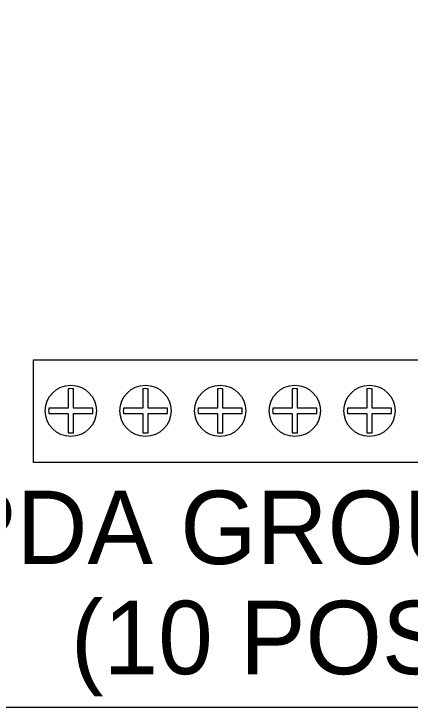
# Model space of a CAD drawing. Extents: x 99862 to 103680, y 99470 to 102076.
# Drawn here: x 101152.8 to 101239.1, y 101106.5 to 101257.6 of the extents above; entities that cross this region are included whole.
import ezdxf

# ---------------------------------------------------------------- set-up
doc = ezdxf.new("R2010")
doc.units = 0
doc.layers.add('Level 20', color=7, linetype='Continuous')
doc.layers.add('Level 26', color=7, linetype='Continuous')

msp = doc.modelspace()

# ---------------------------------------------------------------- linework, layer by layer
at = {"layer": 'Level 26'}
for p, q in [((101164.64, 101174.4), (101164.64, 101171.65)), ((101165.76, 101171.65), (101165.76, 101174.4)), ((101180.91, 101174.4), (101180.91, 101171.65)), ((101182.03, 101171.65), (101182.03, 101174.4)), ((101197.18, 101174.4), (101197.18, 101171.65)), ((101198.3, 101171.65), (101198.3, 101174.4)), ((101213.45, 101174.4), (101213.45, 101171.65)), ((101214.57, 101171.65), (101214.57, 101174.4)), ((101229.72, 101174.4), (101229.72, 101171.65)), ((101230.84, 101171.65), (101230.84, 101174.4)), ((101164.64, 101171.65), (101161.89, 101171.65)), ((101168.5, 101171.65), (101165.76, 101171.65)), ((101180.91, 101171.65), (101178.16, 101171.65)), ((101184.77, 101171.65), (101182.03, 101171.65)), ((101197.18, 101171.65), (101194.43, 101171.65)), ((101201.04, 101171.65), (101198.3, 101171.65)), ((101213.45, 101171.65), (101210.71, 101171.65)), ((101217.31, 101171.65), (101214.57, 101171.65)), ((101229.72, 101171.65), (101226.98, 101171.65)), ((101233.58, 101171.65), (101230.84, 101171.65)), ((101161.89, 101170.53), (101164.64, 101170.53)), ((101164.64, 101170.53), (101164.64, 101167.79)), ((101165.76, 101167.79), (101165.76, 101170.53)), ((101165.76, 101170.53), (101168.5, 101170.53)), ((101178.16, 101170.53), (101180.91, 101170.53)), ((101180.91, 101170.53), (101180.91, 101167.79)), ((101182.03, 101167.79), (101182.03, 101170.53)), ((101182.03, 101170.53), (101184.77, 101170.53)), ((101194.43, 101170.53), (101197.18, 101170.53)), ((101197.18, 101170.53), (101197.18, 101167.79)), ((101198.3, 101167.79), (101198.3, 101170.53)), ((101198.3, 101170.53), (101201.04, 101170.53)), ((101210.71, 101170.53), (101213.45, 101170.53)), ((101213.45, 101170.53), (101213.45, 101167.79)), ((101214.57, 101167.79), (101214.57, 101170.53)), ((101214.57, 101170.53), (101217.31, 101170.53)), ((101226.98, 101170.53), (101229.72, 101170.53)), ((101229.72, 101170.53), (101229.72, 101167.79)), ((101230.84, 101167.79), (101230.84, 101170.53)), ((101230.84, 101170.53), (101233.58, 101170.53))]:
    msp.add_line(p, q, dxfattribs=at)
for points in [[(101878.1, 101455.48), (101003.1, 101455.48), (101003.1, 101106.48), (101878.1, 101106.48)], [(101157.06, 101159.82), (101157.06, 101182.19), (101321.32, 101182.19), (101321.32, 101159.82)]]:
    msp.add_lwpolyline(points, close=True, dxfattribs=at)
for centre in [(101165.2, 101171.09), (101181.47, 101171.09), (101197.74, 101171.09), (101214.01, 101171.09), (101230.28, 101171.09)]:
    msp.add_circle(centre, 5.58, dxfattribs=at)
for centre, start, end in [((101165.2, 101171.09), 83.3581, 96.6419), ((101181.47, 101171.09), 83.3581, 96.6419), ((101197.74, 101171.09), 83.3581, 96.6419), ((101214.01, 101171.09), 83.3581, 96.6419), ((101230.28, 101171.09), 83.3581, 96.6419), ((101165.2, 101171.09), 173.3581, 186.6419), ((101165.2, 101171.09), 353.3581, 6.6419), ((101181.47, 101171.09), 173.3581, 186.6419), ((101181.47, 101171.09), 353.3581, 6.6419), ((101197.74, 101171.09), 173.3581, 186.6419), ((101197.74, 101171.09), 353.3581, 6.6419), ((101214.01, 101171.09), 173.3581, 186.6419), ((101214.01, 101171.09), 353.3581, 6.6419), ((101230.28, 101171.09), 173.3581, 186.6419), ((101230.28, 101171.09), 353.3581, 6.6419), ((101165.2, 101171.09), 263.3581, 276.6419), ((101181.47, 101171.09), 263.3581, 276.6419), ((101197.74, 101171.09), 263.3581, 276.6419), ((101214.01, 101171.09), 263.3581, 276.6419), ((101230.28, 101171.09), 263.3581, 276.6419)]:
    msp.add_arc(centre, 4.83, start, end, dxfattribs=at)
for points in [[(101164.64, 101175.89), (101164.64, 101175.76), (101164.64, 101175.63), (101164.64, 101175.48), (101164.64, 101175.25), (101164.64, 101175), (101164.64, 101174.75), (101164.64, 101174.63), (101164.64, 101174.51), (101164.64, 101174.4)], [(101165.76, 101174.4), (101165.76, 101174.64), (101165.76, 101174.89), (101165.76, 101175.12), (101165.76, 101175.36), (101165.76, 101175.59), (101165.76, 101175.78), (101165.76, 101175.82), (101165.76, 101175.85), (101165.76, 101175.89)], [(101180.91, 101175.89), (101180.91, 101175.76), (101180.91, 101175.63), (101180.91, 101175.48), (101180.91, 101175.25), (101180.91, 101175), (101180.91, 101174.75), (101180.91, 101174.63), (101180.91, 101174.51), (101180.91, 101174.4)], [(101182.03, 101174.4), (101182.03, 101174.64), (101182.03, 101174.89), (101182.03, 101175.12), (101182.03, 101175.36), (101182.03, 101175.59), (101182.03, 101175.78), (101182.03, 101175.82), (101182.03, 101175.85), (101182.03, 101175.89)], [(101197.18, 101175.89), (101197.18, 101175.76), (101197.18, 101175.63), (101197.18, 101175.48), (101197.18, 101175.25), (101197.18, 101175), (101197.18, 101174.75), (101197.18, 101174.63), (101197.18, 101174.51), (101197.18, 101174.4)], [(101198.3, 101174.4), (101198.3, 101174.64), (101198.3, 101174.89), (101198.3, 101175.12), (101198.3, 101175.36), (101198.3, 101175.59), (101198.3, 101175.78), (101198.3, 101175.82), (101198.3, 101175.85), (101198.3, 101175.89)], [(101213.45, 101175.89), (101213.45, 101175.76), (101213.45, 101175.63), (101213.45, 101175.48), (101213.45, 101175.25), (101213.45, 101175), (101213.45, 101174.75), (101213.45, 101174.63), (101213.45, 101174.51), (101213.45, 101174.4)], [(101214.57, 101174.4), (101214.57, 101174.64), (101214.57, 101174.89), (101214.57, 101175.12), (101214.57, 101175.36), (101214.57, 101175.59), (101214.57, 101175.78), (101214.57, 101175.82), (101214.57, 101175.85), (101214.57, 101175.89)], [(101229.72, 101175.89), (101229.72, 101175.76), (101229.72, 101175.63), (101229.72, 101175.48), (101229.72, 101175.25), (101229.72, 101175), (101229.72, 101174.75), (101229.72, 101174.63), (101229.72, 101174.51), (101229.72, 101174.4)], [(101230.84, 101174.4), (101230.84, 101174.64), (101230.84, 101174.89), (101230.84, 101175.12), (101230.84, 101175.36), (101230.84, 101175.59), (101230.84, 101175.78), (101230.84, 101175.82), (101230.84, 101175.85), (101230.84, 101175.89)], [(101161.89, 101171.65), (101161.89, 101171.65), (101161.89, 101171.65), (101161.89, 101171.65), (101161.64, 101171.65), (101161.38, 101171.65), (101161.14, 101171.65), (101160.91, 101171.65), (101160.68, 101171.65), (101160.48, 101171.65), (101160.45, 101171.65), (101160.43, 101171.65), (101160.4, 101171.65)], [(101169.99, 101171.65), (101169.87, 101171.65), (101169.73, 101171.65), (101169.58, 101171.65), (101169.36, 101171.65), (101169.11, 101171.65), (101168.85, 101171.65), (101168.74, 101171.65), (101168.62, 101171.65), (101168.5, 101171.65)], [(101178.16, 101171.65), (101178.16, 101171.65), (101178.16, 101171.65), (101178.16, 101171.65), (101177.91, 101171.65), (101177.65, 101171.65), (101177.41, 101171.65), (101177.18, 101171.65), (101176.95, 101171.65), (101176.75, 101171.65), (101176.72, 101171.65), (101176.7, 101171.65), (101176.67, 101171.65)], [(101186.26, 101171.65), (101186.14, 101171.65), (101186, 101171.65), (101185.86, 101171.65), (101185.63, 101171.65), (101185.38, 101171.65), (101185.12, 101171.65), (101185.01, 101171.65), (101184.89, 101171.65), (101184.77, 101171.65)], [(101194.43, 101171.65), (101194.43, 101171.65), (101194.43, 101171.65), (101194.43, 101171.65), (101194.18, 101171.65), (101193.92, 101171.65), (101193.69, 101171.65), (101193.45, 101171.65), (101193.22, 101171.65), (101193.02, 101171.65), (101193, 101171.65), (101192.97, 101171.65), (101192.94, 101171.65)], [(101202.53, 101171.65), (101202.41, 101171.65), (101202.27, 101171.65), (101202.13, 101171.65), (101201.9, 101171.65), (101201.65, 101171.65), (101201.39, 101171.65), (101201.28, 101171.65), (101201.16, 101171.65), (101201.04, 101171.65)], [(101210.71, 101171.65), (101210.7, 101171.65), (101210.7, 101171.65), (101210.7, 101171.65), (101210.45, 101171.65), (101210.19, 101171.65), (101209.96, 101171.65), (101209.72, 101171.65), (101209.49, 101171.65), (101209.29, 101171.65), (101209.27, 101171.65), (101209.24, 101171.65), (101209.21, 101171.65)], [(101218.8, 101171.65), (101218.68, 101171.65), (101218.54, 101171.65), (101218.4, 101171.65), (101218.17, 101171.65), (101217.92, 101171.65), (101217.66, 101171.65), (101217.55, 101171.65), (101217.43, 101171.65), (101217.31, 101171.65)], [(101226.98, 101171.65), (101226.98, 101171.65), (101226.97, 101171.65), (101226.97, 101171.65), (101226.72, 101171.65), (101226.47, 101171.65), (101226.23, 101171.65), (101225.99, 101171.65), (101225.76, 101171.65), (101225.56, 101171.65), (101225.54, 101171.65), (101225.51, 101171.65), (101225.48, 101171.65)], [(101235.08, 101171.65), (101234.95, 101171.65), (101234.81, 101171.65), (101234.67, 101171.65), (101234.44, 101171.65), (101234.19, 101171.65), (101233.94, 101171.65), (101233.82, 101171.65), (101233.7, 101171.65), (101233.58, 101171.65)], [(101160.4, 101170.53), (101160.43, 101170.53), (101160.45, 101170.53), (101160.48, 101170.53), (101160.6, 101170.53), (101160.73, 101170.53), (101160.87, 101170.53), (101161.1, 101170.53), (101161.36, 101170.53), (101161.61, 101170.53), (101161.71, 101170.53), (101161.8, 101170.53), (101161.89, 101170.53)], [(101168.5, 101170.53), (101168.75, 101170.53), (101168.99, 101170.53), (101169.22, 101170.53), (101169.46, 101170.53), (101169.69, 101170.53), (101169.89, 101170.53), (101169.92, 101170.53), (101169.96, 101170.53), (101169.99, 101170.53)], [(101176.67, 101170.53), (101176.7, 101170.53), (101176.72, 101170.53), (101176.75, 101170.53), (101176.87, 101170.53), (101177.01, 101170.53), (101177.14, 101170.53), (101177.37, 101170.53), (101177.63, 101170.53), (101177.89, 101170.53), (101177.98, 101170.53), (101178.07, 101170.53), (101178.16, 101170.53)], [(101184.77, 101170.53), (101185.02, 101170.53), (101185.26, 101170.53), (101185.5, 101170.53), (101185.73, 101170.53), (101185.96, 101170.53), (101186.16, 101170.53), (101186.19, 101170.53), (101186.23, 101170.53), (101186.26, 101170.53)], [(101192.94, 101170.53), (101192.97, 101170.53), (101193, 101170.53), (101193.02, 101170.53), (101193.14, 101170.53), (101193.28, 101170.53), (101193.41, 101170.53), (101193.65, 101170.53), (101193.9, 101170.53), (101194.16, 101170.53), (101194.25, 101170.53), (101194.34, 101170.53), (101194.43, 101170.53)], [(101201.04, 101170.53), (101201.29, 101170.53), (101201.53, 101170.53), (101201.77, 101170.53), (101202, 101170.53), (101202.23, 101170.53), (101202.43, 101170.53), (101202.46, 101170.53), (101202.5, 101170.53), (101202.53, 101170.53)], [(101209.21, 101170.53), (101209.24, 101170.53), (101209.27, 101170.53), (101209.29, 101170.53), (101209.41, 101170.53), (101209.55, 101170.53), (101209.69, 101170.53), (101209.92, 101170.53), (101210.17, 101170.53), (101210.43, 101170.53), (101210.52, 101170.53), (101210.61, 101170.53), (101210.71, 101170.53)], [(101217.31, 101170.53), (101217.56, 101170.53), (101217.81, 101170.53), (101218.04, 101170.53), (101218.27, 101170.53), (101218.5, 101170.53), (101218.7, 101170.53), (101218.74, 101170.53), (101218.77, 101170.53), (101218.8, 101170.53)], [(101225.48, 101170.53), (101225.51, 101170.53), (101225.54, 101170.53), (101225.56, 101170.53), (101225.68, 101170.53), (101225.82, 101170.53), (101225.96, 101170.53), (101226.19, 101170.53), (101226.44, 101170.53), (101226.7, 101170.53), (101226.79, 101170.53), (101226.88, 101170.53), (101226.98, 101170.53)], [(101233.58, 101170.53), (101233.83, 101170.53), (101234.08, 101170.53), (101234.31, 101170.53), (101234.54, 101170.53), (101234.77, 101170.53), (101234.97, 101170.53), (101235.01, 101170.53), (101235.04, 101170.53), (101235.08, 101170.53)], [(101164.64, 101167.79), (101164.64, 101167.79), (101164.64, 101167.79), (101164.64, 101167.79), (101164.64, 101167.54), (101164.64, 101167.28), (101164.64, 101167.04), (101164.64, 101166.8), (101164.64, 101166.57), (101164.64, 101166.38), (101164.64, 101166.35), (101164.64, 101166.32), (101164.64, 101166.3)], [(101165.76, 101166.3), (101165.76, 101166.32), (101165.76, 101166.35), (101165.76, 101166.38), (101165.76, 101166.5), (101165.76, 101166.63), (101165.76, 101166.77), (101165.76, 101167), (101165.76, 101167.25), (101165.76, 101167.51), (101165.76, 101167.6), (101165.76, 101167.7), (101165.76, 101167.79)], [(101180.91, 101167.79), (101180.91, 101167.79), (101180.91, 101167.79), (101180.91, 101167.79), (101180.91, 101167.54), (101180.91, 101167.28), (101180.91, 101167.04), (101180.91, 101166.8), (101180.91, 101166.57), (101180.91, 101166.38), (101180.91, 101166.35), (101180.91, 101166.32), (101180.91, 101166.3)], [(101182.03, 101166.3), (101182.03, 101166.32), (101182.03, 101166.35), (101182.03, 101166.38), (101182.03, 101166.5), (101182.03, 101166.63), (101182.03, 101166.77), (101182.03, 101167), (101182.03, 101167.25), (101182.03, 101167.51), (101182.03, 101167.6), (101182.03, 101167.7), (101182.03, 101167.79)], [(101197.18, 101167.79), (101197.18, 101167.79), (101197.18, 101167.79), (101197.18, 101167.79), (101197.18, 101167.54), (101197.18, 101167.28), (101197.18, 101167.04), (101197.18, 101166.8), (101197.18, 101166.57), (101197.18, 101166.38), (101197.18, 101166.35), (101197.18, 101166.32), (101197.18, 101166.3)], [(101198.3, 101166.3), (101198.3, 101166.32), (101198.3, 101166.35), (101198.3, 101166.38), (101198.3, 101166.5), (101198.3, 101166.63), (101198.3, 101166.77), (101198.3, 101167), (101198.3, 101167.25), (101198.3, 101167.51), (101198.3, 101167.6), (101198.3, 101167.7), (101198.3, 101167.79)], [(101213.45, 101167.79), (101213.45, 101167.79), (101213.45, 101167.79), (101213.45, 101167.79), (101213.45, 101167.54), (101213.45, 101167.28), (101213.45, 101167.04), (101213.45, 101166.8), (101213.45, 101166.57), (101213.45, 101166.38), (101213.45, 101166.35), (101213.45, 101166.32), (101213.45, 101166.3)], [(101214.57, 101166.3), (101214.57, 101166.32), (101214.57, 101166.35), (101214.57, 101166.38), (101214.57, 101166.5), (101214.57, 101166.63), (101214.57, 101166.77), (101214.57, 101167), (101214.57, 101167.25), (101214.57, 101167.51), (101214.57, 101167.6), (101214.57, 101167.7), (101214.57, 101167.79)], [(101229.72, 101167.79), (101229.72, 101167.79), (101229.72, 101167.79), (101229.72, 101167.79), (101229.72, 101167.54), (101229.72, 101167.28), (101229.72, 101167.04), (101229.72, 101166.8), (101229.72, 101166.57), (101229.72, 101166.38), (101229.72, 101166.35), (101229.72, 101166.32), (101229.72, 101166.3)], [(101230.84, 101166.3), (101230.84, 101166.32), (101230.84, 101166.35), (101230.84, 101166.38), (101230.84, 101166.5), (101230.84, 101166.63), (101230.84, 101166.77), (101230.84, 101167), (101230.84, 101167.25), (101230.84, 101167.51), (101230.84, 101167.6), (101230.84, 101167.7), (101230.84, 101167.79)]]:
    msp.add_open_spline(points, degree=3, dxfattribs=at)

# ---------------------------------------------------------------- texts
at = {"layer": 'Level 20'}
for s, p in [('PDA GROUND BUS', (101139.11, 101137.67)), ('(10 POSITION)', (101165.21, 101113.67))]:
    msp.add_text(s, height=16, dxfattribs=at).set_placement(p)

doc.saveas('drawing.dxf')
